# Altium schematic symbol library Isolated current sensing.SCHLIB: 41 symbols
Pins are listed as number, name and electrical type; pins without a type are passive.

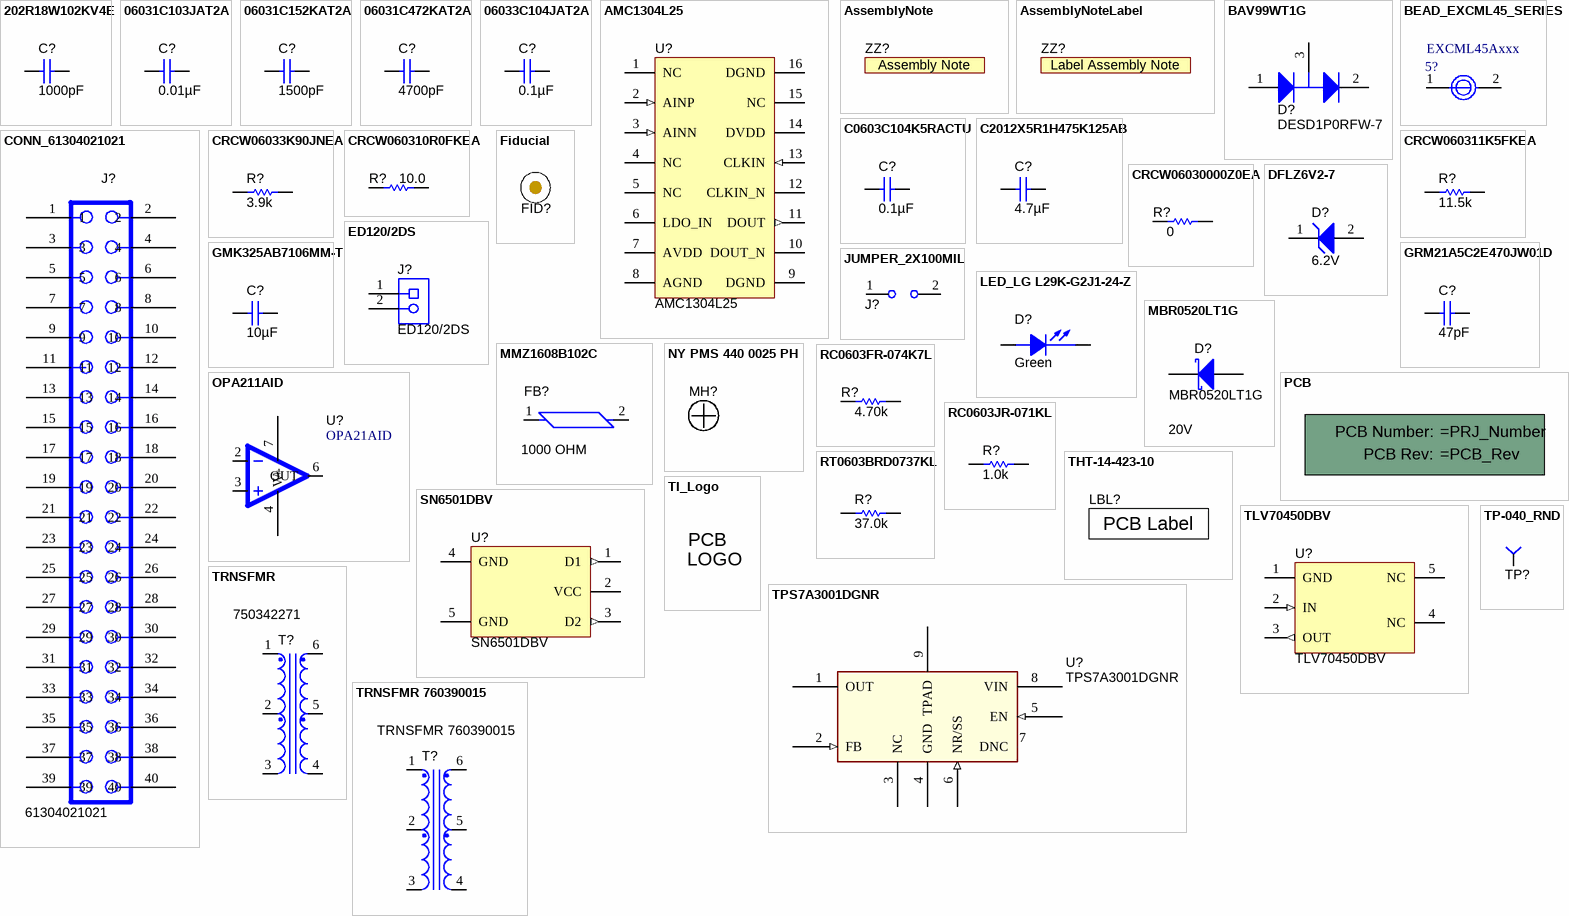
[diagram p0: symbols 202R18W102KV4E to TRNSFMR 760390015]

## 202R18W102KV4E
designator C?  value 1000pF
CAP, CERM, 1000pF, 2KV 10% X7R 1206; PartNumber: 202R18W102KV4E; Manufacturer: Johanson Dielectrics Inc; Polarized: N; CompType: Capacitor; Cap_F: 0.000000001; Tolerance_%: 0; Cap_Case: 1206
signal-integrity model Cap
simulation model Cap
footprint 1206
footprint 1206M
footprint 1206L
pins: 1, 2

## 06031C103JAT2A
designator C?  ValueDisplayed: 0.01µF
CAP, CERM, 0.01uF, 100V, +/-5%, X7R, 0603; PartNumber: 06031C103JAT2A; Manufacturer: AVX; Polarized: N; CompType: Capacitor; U/M: EA; Cap_F: 0.00000001; Tolerance_%: 5; ESR_Ohm: 0.098; Value1: 0.098 ohm; VDC_V: 100; TaMin_C: -55; TaMax_C: 125; Cap_Case: 0603
signal-integrity model Cap
simulation model Cap
footprint 0603
footprint 0603M
footprint 0603L
footprint 0603_HV
pins: 1, 2

## 06031C152KAT2A
designator C?  ValueDisplayed: 1500pF  (hidden comment: 06031C152KAT2A)
CAP, CERM, 1500pF, 100V, +/-10%, X7R, 0603; Manufacturer: AVX; Polarized: N; CompType: Capacitor; U/M: EA; Cap_F: 0.0000000015; Tolerance_%: 10; ESR_Ohm: 0.229; Value1: 0.229 ohm; VDC_V: 100; TaMin_C: -55; TaMax_C: 125; Cap_Case: 0603
signal-integrity model Cap
simulation model Cap
footprint 0603
footprint 0603M
footprint 0603L
footprint 0603_HV
pins: 1, 2

## 06031C472KAT2A
designator C?  ValueDisplayed: 4700pF
CAP, CERM, 4700pF, 100V, +/-10%, X7R, 0603; PartNumber: 06031C472KAT2A; Manufacturer: AVX; Polarized: N; CompType: Capacitor; U/M: EA; Cap_F: 0.0000000047; Tolerance_%: 10; ESR_Ohm: 0.136; Value1: 0.136 ohm; VDC_V: 100; TaMin_C: -55; TaMax_C: 125; Cap_Case: 0603
signal-integrity model Cap
simulation model Cap
footprint 0603
footprint 0603M
footprint 0603L
footprint 0603_HV
pins: 1, 2

## 06033C104JAT2A
designator C?  ValueDisplayed: 0.1µF
CAP, CERM, 0.1uF, 25V, +/-5%, X7R, 0603; PartNumber: 06033C104JAT2A; Manufacturer: AVX; Polarized: N; CompType: Capacitor; U/M: EA; Cap_F: 0.0000001; Tolerance_%: 5; ESR_Ohm: 0.05; Value1: 0.05 ohm; VDC_V: 25; TaMin_C: -55; TaMax_C: 125; Cap_Case: 0603
signal-integrity model Cap
simulation model Cap
footprint 0603
footprint 0603M
footprint 0603L
footprint 0603_HV
pins: 1, 2

## AMC1304L25
designator U?
20 MHz, Isolated Delta-Sigma Modulator, LVDS interface:; Alternate Manufacturer: None; Manufacturer: Texas Instruments; SymbolCreator: x0120606; CompType: IC
footprint DW0016A_N
footprint DW0016A_M
footprint DW0016A_L
pins: 1 NC (power), 2 AINP (in), 3 AINN (in), 4 NC (power), 5 NC, 6 LDO_IN, 7 AVDD, 8 AGND, 9 DGND (power), 10 DOUT_N, 11 DOUT (out), 12 CLKIN_N, 13 CLKIN (in), 14 DVDD (power), 15 NC, 16 DGND (power)

## AssemblyNote
designator ZZ?  (no BOM)
These assemblies are ESD sensitive, ESD precautions shall be observed.; SymbolCreator: codlsc; CompType: AssemblyNote
footprint AssemblyNote

## AssemblyNoteLabel
designator ZZ?  (no BOM)
This Assembly Note is for PCB labels only; SymbolCreator: a0412235
footprint AssemblyNoteLabel

## BAV99WT1G
designator D?, comment DESD1P0RFW-7
Diode, P-N, 70V, 0.2A, SOT-323; Manufacturer: Diodes Inc; Value: DNP
footprint SOT-323
pins: 1 A, 2 K, 3 C
1 alternate drawing of the same symbol

## BEAD_EXCML45_SERIES
designator 5?, comment EXCML45Axxx
Bead, SMD 3A, Low DC Resistance; Manufacturer: Panasonic; Area: 26400
footprint 1806
pins: 1, 2

## C0603C104K5RACTU
designator C?  ValueDisplayed: 0.1µF
CAP, CERM, 0.1uF, 50V, +/-10%, X7R, 0603; PartNumber: C0603C104K5RACTU; Manufacturer: Kemet; Polarized: N; CompType: Capacitor; U/M: EA; Cap_F: 0.0000001; Tolerance_%: 10; Value1: Unknown; VDC_V: 50; TaMin_C: -55; TaMax_C: 125; Cap_Case: 0603
signal-integrity model Cap
simulation model Cap
footprint 0603
footprint 0603M
footprint 0603L
footprint 0603_HV
pins: 1, 2

## C2012X5R1H475K125AB
designator C?  ValueDisplayed: 4.7µF
CAP, CERM, 4.7uF, 50V, +/-10%, X5R, 0805; PartNumber: C2012X5R1H475K125AB; Manufacturer: TDK; Polarized: N; CompType: Capacitor; U/M: EA; Cap_F: 0.0000047; Tolerance_%: 10; Value1: Unknown; VDC_V: 50; TaMin_C: -55; TaMax_C: 85; Cap_Case: 0805
signal-integrity model Cap
simulation model Cap
footprint 0805_HV
footprint 0805
footprint 0805M
footprint 0805L
pins: 1, 2

## CONN_61304021021
designator J?, comment 61304021021
Connector, Right Angle 2x20 pin, 100mil spacing; Manufacturer: WURTH ELEKTRONIK; area: 1.262.250
footprint CONN_61304021021
pins: 1, 2, 3, 4, 5, 6, 7, 8, 9, 10, 11, 12, 13, 14, 15, 16, 17, 18, 19, 20, 21, 22, 23, 24, 25, 26, 27, 28, 29, 30, 31, 32, 33, 34, 35, 36, 37, 38, 39, 40

## CRCW06033K90JNEA
designator R?  value 3.9k
RES, 3.9k ohm, 5%, 0.1W, 0603; PartNumber: CRCW06033K90JNEA; Manufacturer: Vishay-Dale; CompType: Resistor; Res_ohm: 3900; Value_Code: 3k90; Tolerance_%: 5; Power_W: 0.1; VDC_V: 75; TempCo: 200 ppm/C; EIA_Code: E24; U/M: EA
signal-integrity model Resistor
simulation model Resistor
footprint 0603
footprint 0603M
footprint 0603L
footprint 0603_HV
footprint 0603
footprint 0603_HV
footprint 0603L
footprint 0603M
simulation model Resistor
signal-integrity model Resistor
pins: 1, 2

## CRCW060310R0FKEA
designator R?  value 10.0
RES, 10.0 ohm, 1%, 0.1W, 0603; PartNumber: CRCW060310R0FKEA; Manufacturer: Vishay-Dale; CompType: Resistor; Res_ohm: 10; Value_Code: 10R0; Tolerance_%: 1; Power_W: 0.1; VDC_V: 75; TempCo: 100 ppm/C; EIA_Code: E96; U/M: EA
signal-integrity model Resistor
simulation model Resistor
footprint 0603
footprint 0603M
footprint 0603L
footprint 0603_HV
pins: 1, 2

## CRCW060311K5FKEA
designator R?  value 11.5k
RES, 11.5k ohm, 1%, 0.1W, 0603; PartNumber: CRCW060311K5FKEA; Manufacturer: Vishay-Dale; CompType: Resistor; Res_ohm: 11500; Value_Code: 11k5; Tolerance_%: 1; Power_W: 0.1; VDC_V: 75; TempCo: 100 ppm/C; EIA_Code: E96; U/M: EA
signal-integrity model Resistor
simulation model Resistor
footprint 0603
footprint 0603M
footprint 0603L
footprint 0603_HV
pins: 1, 2

## CRCW06030000Z0EA
designator R?  value 0
RES, 0 ohm, 5%, 0.1W, 0603; PartNumber: CRCW06030000Z0EA; Manufacturer: Vishay-Dale; CompType: Resistor; Value_Code: 0000; Tolerance_%: 5; Power_W: 0.1; VDC_V: 75; TempCo: 200 ppm/C; EIA_Code: E24; U/M: EA
signal-integrity model Resistor
simulation model Resistor
footprint 0603
footprint 0603M
footprint 0603L
footprint 0603_HV
pins: 1, 2

## DFLZ6V2-7
designator D?  value 6.2V
Diode, Zener, 6.2V, 1W, PowerDI123; PartNumber: DFLZ6V2-7; Manufacturer: Diodes Inc.; U/M: EA; Power_W: 1; Vz_V: 6.2; RJA_CperW: 110
signal-integrity model Diode
footprint powerDI123
pins: 1 K, 2 A

## ED120/2DS
designator J?
TERMINAL BLOCK 5.08MM VERT 2POS, TH; Manufacturer: On-Shore Technology; SymbolCreator: a0412235; U/M: EA
footprint CONN_ED120-2DS
pins: 1, 2

## Fiducial
designator FID?
Fiducial mark.  There is nothing to buy or mount.; SymbolCreator: codlsc
footprint Fiducial10-30
footprint Fiducial10-20
footprint Fiducial15-30
footprint Fiducial20-40
footprint Fiducial6.4-20
footprint Fiducial10-30_TopLayerKeepOutOnly
footprint Fiducial6.4-20_TopLayerKeepOutOnly
footprint Fiducial10-20_TopLayerKeepOutOnly
footprint Fiducial15-30_TopLayerKeepOutOnly
footprint Fiducial20-40_TopLayerKeepOutOnly

## GMK325AB7106MM-T
designator C?  ValueDisplayed: 10µF
CAP, CERM, 10uF, 35V, +/-20%, X7R, 1210; PartNumber: GMK325AB7106MM-T; Manufacturer: Taiyo Yuden; Polarized: N; CompType: Capacitor; U/M: EA; Cap_F: 0.00001; Tolerance_%: 20; Value1: Unknown; VDC_V: 35; TaMin_C: -55; TaMax_C: 125; Cap_Case: 1210
signal-integrity model Cap
simulation model Cap
footprint 1210
footprint 1210M
footprint 1210L
pins: 1, 2

## GRM21A5C2E470JW01D
designator C?  ValueDisplayed: 47pF  (hidden comment: GRM21A5C2E470JW01D)
CAP, CERM, 47pF, 500V, +/-5%, C0G/NP0, 0805; Manufacturer: MuRata; Polarized: N; CompType: Capacitor; U/M: EA; Cap_F: 0.000000000047; Tolerance_%: 5; Value1: Unknown; VDC_V: 250; Value2: 250V; TaMin_C: -55; TaMax_C: 125; Cap_Case: 0805
signal-integrity model Cap
simulation model Cap
footprint 0805_HV
footprint 0805
footprint 0805M
footprint 0805L
pins: 1, 2

## JUMPER_2X100MIL
designator J?
Header, Male 2-pin, 100mil spacing,; Manufacturer: Sullins; PartNumber: PEC02SAAN; area: 20000; Value: PEC02SAAN
footprint HDR100_1X2
pins: 1, 2

## LED_LG L29K-G2J1-24-Z
designator D?  value Green
LED SmartLED Green 570NM; PartNumber: LG L29K-G2J1-24-Z; Manufacturer: OSRAM; SymbolCreator: x0120606
footprint LED0603AA
pins: 1 C, 2 A

## MBR0520LT1G
designator D?  value 20V
Diode, Schottky, 20V, 0.5A, SOD-123; Manufacturer: ON Semiconductor; U/M: EA; Vf_V: 0.385; Value2: 0.385V; Io_A: 0.5; Vr_V: 20; TJmax_C: 125; RJC_CperW: 150
signal-integrity model Diode
simulation model mbr0520lt1
footprint SOD-123
pins: 1 K, 2 A

## MMZ1608B102C
designator FB?  value 1000 OHM
FERRITE CHIP 1000 OHM 300MA 0603; PartNumber: MMZ1608B102C; Manufacturer: TDK Corporation; CompType: Ferrite Bead
footprint FB0603
pins: 1, 2

## NY PMS 440 0025 PH
designator MH?
Mountin hole, NPTH Drill 3.2mm; CompType: Hardware
footprint NY PMS 440 0025 PH
footprint MH3.2

## OPA211AID
designator U?, comment OPA21AID
IC, 1.1nV/vHz Noise, Low Power, Precision OpAmp; PartNumber: OPA211ID; Manufacturer: TI; Alternate Manufacturer: None; Area: 75900; Value: OPA211ID
footprint SO8
pins: 2, 3, 4 V-, 6 OUT, 7 V+

## PCB
designator !PCB?  (mechanical)
Printed Circuit Board; Manufacturer: Any; SymbolCreator: a0412235; CompType: PCB
1 alternate drawing of the same symbol

## RC0603FR-074K7L
designator R?  value 4.70k
RES, 4.70k ohm, 1%, 0.1W, 0603; PartNumber: RC0603FR-074K7L; Manufacturer: Yageo America; CompType: Resistor; Res_ohm: 4700; Value_Code: 4k70; Tolerance_%: 1; Power_W: 0.1; VDC_V: 150; TempCo: 200 ppm/C; U/M: EA
signal-integrity model Resistor
simulation model Resistor
footprint 0603
footprint 0603M
footprint 0603L
footprint 0603_HV
pins: 1, 2

## RC0603JR-071KL
designator R?  value 1.0k  (hidden comment: RC0603JR-071KL)
RES, 1.0k ohm, 5%, 0.1W, 0603; Manufacturer: Yageo America; CompType: Resistor; Res_ohm: 1000; Value_Code: 1k00; Tolerance_%: 5; Power_W: 0.1; VDC_V: 50; TempCo: 100 ppm/C; EIA_Code: E24; U/M: EA
signal-integrity model Resistor
simulation model Resistor
footprint 0603
footprint 0603M
footprint 0603L
footprint 0603_HV
footprint 0603S
pins: 1, 2

## RT0603BRD0737KL
designator R?  value 37.0k
RES, 37.0k ohm, 0.1%, 0.1W, 0603; PartNumber: RT0603BRD0737KL; Manufacturer: Yageo America; CompType: Resistor; Res_ohm: 37000; Value_Code: 37k0; Tolerance_%: 0.1; VDC_V: 75; TempCo: 25 ppm/C; EIA_Code: E192; U/M: EA
signal-integrity model Resistor
simulation model Resistor
footprint 0603
footprint 0603M
footprint 0603L
footprint 0603_HV
pins: 1, 2

## SN6501DBV
designator U?
Transformer Driver for Isolated Power Supplies, DBV0005A; Alternate Manufacturer: None; Manufacturer: Texas Instruments; SymbolCreator: a0411947; CompType: IC; U/M: EA
footprint DBV0005A_N
footprint DBV0005A_M
footprint DBV0005A_L
pins: 1 D1 (out), 2 VCC (power), 3 D2 (out), 4 GND (power), 5 GND (power)

## THT-14-423-10
designator LBL?
Thermal Transfer Printable Labels, 0.650" W x 0.200" H - 10,000 per roll; Manufacturer: Brady; PartNumber: THT-14-423-10; SymbolCreator: a0412235; CompType: Label; Note: Size: 0.65" x 0.20 "
footprint Label_650x200

## TI_Logo
designator Logo?  (no BOM)
Texas Instrument Corporate Signature; SymbolCreator: codlsc
footprint TI_Stacked_SolderMask_Medium
footprint TI_Stacked_SolderMask_Small
footprint TI_Stacked_Overlay_Medium
footprint TI_Stacked_Overlay_Small
footprint TI_Horizontal_SolderMask_Medium
footprint TI_Horizontal_SolderMask_Small
footprint TI_Horizontal_Overlay_Medium
footprint TI_Horizontal_Overlay_Small
footprint TI_Symbol_SolderMask_Small
footprint TI_Symbol_Overlay_Medium
footprint TI_Symbol_Overlay_Small
footprint TI_Symbol_SolderMask_Medium

## TLV70450DBV
designator U?
Regulator, LDO, 5V, 0.15A, SOT23-5; Alternate Manufacturer: None; Manufacturer: Texas Instruments; SymbolCreator: x0120606; CompType: IC
footprint DBV0005A_N (SOT23, 5-Leads, Body 2.9x1.6mm, Pitch 0.95mm, Lead Span 2.8mm, IPC Medium Density)
pins: 1 GND (power), 2 IN (in), 3 OUT (out), 4 NC (power), 5 NC (power)
1 alternate drawing of the same symbol

## TP-040_RND
designator TP?
Test Point, O.040 Hole; Manufacturer: STD; Value: STD
footprint TP-040_RND
pins: 1

## TPS7A3001DGNR
designator U?
-36V, -200mA, Ultralow-Noise, Negative Linear Regulator; Alternate Manufacturer: None; Manufacturer: Texas Instruments; CompType: IC; SymbolCreator: x0120606
footprint MSOP8(DGN)
pins: 1 OUT (power), 2 FB (in), 3 NC, 4 GND (power), 5 EN (in), 6 NR/SS (in), 7 DNC, 8 VIN (power), 9 TPAD

## TRNSFMR
designator T?, comment 750342271
Transformer 469uH SMD; Manufacturer: Wurth Electronics Midcom
footprint 760390015
pins: 1, 2, 3, 4, 5, 6

## TRNSFMR 760390015
designator T?
Transformer 469uH SMD; PartNumber: 750342271; Manufacturer: Wurth Electronics Midcom
footprint 760390015
pins: 1, 2, 3, 4, 5, 6

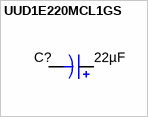
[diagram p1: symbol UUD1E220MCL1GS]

## UUD1E220MCL1GS
designator C?  ValueDisplayed: 22µF  (hidden comment: UUD1E220MCL1GS)
CAP, AL, 22uF, 25V, +/-20%, 0.76 ohm, SMD; Manufacturer: Nichicon; Polarized: Y; CompType: Capacitor; U/M: EA; Cap_F: 0.000022; Tolerance_%: 20; VDC_V: 25; ESR_Ohm: 0.76; IRMS_A: 0.15; TaMin_C: -55; TaMax_C: 105; Cap_Case: 5x5.8
signal-integrity model Cap
simulation model Cap
footprint SM_RADIAL_5MM
pins: 1 +, 2 -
